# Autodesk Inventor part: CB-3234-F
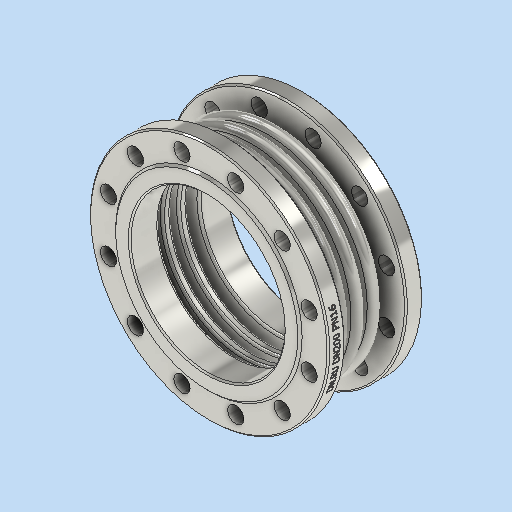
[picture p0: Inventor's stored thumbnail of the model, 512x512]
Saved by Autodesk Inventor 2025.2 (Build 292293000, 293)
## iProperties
Company: DN.RU
Created: 2026-04
Part Number: CB-3234-F
Material: Типовые
Document SubType Name: Modeling
Designer: DN.RU
Density: 6.45609 g/cm^3
Appearance: По умолчанию
Description: D140-02119
Mass: 18500 g
Surface Area: 7834.59 cm^2
Volume: 2865.51 cm^3
Author: DN.RU
Title: Компенсатор сильфонный осевой DN.ru Ду200 Ру16
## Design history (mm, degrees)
sketch "Эскиз1"
  geometry: L1 (0, 0)-(0, -70); L2 (117.5, -70)-(117.5, 0); L3 (117.5, 0)-(0, 0); L4 (117.5, 0)-(117.5, 0); L5 (92.5, 0)-(142.5, 0); L6 (92.5, -7.5)-(142.5, -7.5); L7 (142.5, 7.5)-(92.5, 7.5); L8 (142.5, -5.5)-(92.5, -5.5); L9 (92.5, 5.5)-(142.5, 5.5); L10 (142.5, -15.5)-(92.5, -15.5); L11 (92.5, -17.5)-(142.5, -17.5); L12 (92.5, -23)-(142.5, -23); L13 (92.5, -30.5)-(142.5, -30.5); L14 (142.5, -28.5)-(92.5, -28.5); L15 (0, -70)-(117.5, -70); L16 (117.5, -70)-(109.5, -70); L17 (109.5, -70)-(109.5, -28.5); L18 (117.5, -17.5)-(115.5, -17.5); L19 (115.5, -17.5)-(115.5, -5.5); L20 (117.5, 5.5)-(115.5, 5.5); L21 (115.5, 5.5)-(115.5, 0); L22 (0, -70)-(0, -43); L23 (0, -43)-(170, -43); L24 (170, -43)-(170, -70); L25 (170, -70)-(0, -70); L26 (117.5, -43)-(117.5, -58); L27 (117.5, -58)-(121.5, -58); L28 (121.5, -58)-(121.5, -43); L29 (121.5, -43)-(117.5, -43); L30 (117.5, 0)-(150, 0); A1 r 7.5 centre (92.5, 0) between (92.5, 7.5) and (92.5, -7.5); A2 r 7.5 centre (142.5, 0) between (142.5, -7.5) and (142.5, 7.5); A3 r 5.5 centre (92.5, 0) between (92.5, 5.5) and (92.5, -5.5); A4 r 5.5 centre (142.5, 0) between (142.5, -5.5) and (142.5, 5.5); A5 r 5.5 centre (92.5, -23) between (92.5, -17.5) and (92.5, -28.5); A6 r 7.5 centre (92.5, -23) between (92.5, -15.5) and (92.5, -30.5); A7 r 5.5 centre (142.5, -23) between (142.5, -28.5) and (142.5, -17.5); A8 r 7.5 centre (142.5, -23) between (142.5, -30.5) and (142.5, -15.5); 20 further points
  constraints: 64 end point, 17 point on circle, 14 point on line, 8 centre point, 7 parallel, 5 perpendicular, 4 tangent, 3 midpoint, 2 vertical, 1 horizontal, 25 other
  dimensions: "d0" = 70 distance of L1.start L1.end; "d3" = 0 distance of L2.end L4.end; "d4" = 25 distance of L4.end L5.end; "d5" = 15 diameter of A2; "d6" = 2 distance between parallel lines of L6 L8; "d9" = 23 distance of L4.end point (117.5, -23); "d18" = 2 distance of L18.start L18.end; "d19" = 2 distance of L20.start L20.end; "d27" = 109.5 distance between parallel lines of L1 L17; "d28" = 8 distance between parallel lines of L2 L17; "d29" = 27 distance of L1.end L22.end; "d30" = 170 distance of L22.end L23.end; "d31" = 15 distance of L26.start L26.end; "d32" = 4 distance of L27.end L26.end
revolve "Вращение1" sketch "Эскиз1" stored, may be unused: angle "d20" = 360 deg
sketch "Эскиз3" dims "d33" = 295
  geometry: L1 (0, 0)-(74.331, 19.917); L2 (0, 0)-(76.954, 0); C1 r 11.5 at (142.474, 38.176); C2 r 11.5 at (104.298, 104.298); C3 r 11.5 at (38.176, 142.474); C4 r 11.5 at (-38.176, 142.474); C5 r 109.5 at (0, 0) reference; C6 r 132.5 at (0, 0); C7 r 170 at (0, 0) reference; C8 r 11.5 at (-104.298, 104.298); C9 r 11.5 at (-142.474, 38.176); C10 r 11.5 at (-142.474, -38.176); C11 r 11.5 at (-104.298, -104.298); C12 r 11.5 at (-38.176, -142.474); C13 r 11.5 at (38.176, -142.474); C14 r 11.5 at (104.298, -104.298); C15 r 11.5 at (142.474, -38.176); 1 further point
  constraints: 13 centre point, 4 end point, 2 coincident, 1 equal length, 1 horizontal, 1 point on line, 28 other
  dimensions: "d34" = 15 deg angle of L2 L1; "d35" = 23 diameter of C1; "d38" = 360 deg dimension on point (0, 0) C1.centre (derived); "d40" = 265 diameter of C6
  node "Эскиз — круговой массив1" dims "d38" = 360 deg (derived)
extrude "Выдавливание1" cut sketch "Эскиз3" stored distance "d41" = 10; taper "d42" = 0 deg
extrude "Выдавливание2" cut sketch "Эскиз3" distance "d43" = 3; taper "d44" = 0 deg
chamfer "Фаска2" distance "d45" = 3; stored, may be unused: second distance "d46" = 2, angle "d47" = 45 deg
chamfer "Фаска3" distance "d48" = 2; stored, may be unused: second distance "d49" = 2, angle "d50" = 45 deg
mirror "Зеркальное отражение2"
fillet "Сопряжение2" dims "d51" = 3
node "РабПлоскость2"
sketch "Эскиз4"
  geometry: L1 (-60.476, 3.302)-(81.492, 3.302); L2 (81.492, 3.302)-(81.492, -37.818); L3 (81.492, -37.818)-(-60.476, -37.818); L4 (-60.476, -37.818)-(-60.476, 3.302); 1 further point
  constraints: 2 other
feature "Рельеф2" sketch "Эскиз4" dims "d52" = 0.1, "d53" = 0
feature "ɧ耀ɩ耀ɫ耀ɭ耀ɯ耀ɱ耀ɳ耀ɵ耀" dims "d0" = 70, "d3" = 0, "d4" = 25, "d5" = 15, "d6" = 2, "d7" = 20, "d9" = 23, "d10" = 10, "d12" = 10, "d18" = 2, "d19" = 2, "d20" = 360 deg, "d27" = 109.5, "d28" = 8, "d29" = 27, "d30" = 170, "d31" = 15, "d32" = 4, "d33" = 295, "d34" = 15 deg, "d35" = 23, "d36" = 120, "d38" = 360 deg (derived), "d40" = 265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
node "Твердое тело1"
node "Эскиз — прямоугольный массив1" dims "d9" = 23, "d12" = 10
